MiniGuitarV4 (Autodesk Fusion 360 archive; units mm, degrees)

design "MiniGuitarV4" references "PCB"
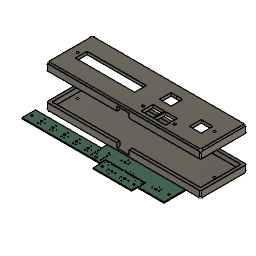
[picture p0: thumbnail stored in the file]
part number: 2026-04-06-11-56-48-601
part number: 2026-04-06-15-34-33-417
part number: 2026-04-06-15-34-33-425
part number: 2026-04-06-15-34-33-428
sketch "Sketch2" plane through (0, 0, 0) normal (0, 0, 1) x axis (1, 0, 0)
sketch "Sketch3" plane through (0, 0, 0) normal (0, 0, 1) x axis (1, 0, 0)
  line L1 (-63.5, -63.5) -> (-63.5, 12.7)
  line L2 (190.5, -63.5) -> (-63.5, -63.5)
  line L3 (190.5, 12.7) -> (190.5, -63.5)
  line L4 (-63.5, 12.7) -> (190.5, 12.7)
  point P2 (-63.5, 12.7)
  point P3 (-63.5, -63.5)
  point P4 (190.5, -63.5)
  vertical L1
  perpendicular L1 L2
  perpendicular L2 L3
  perpendicular L1 L4
  dimension "d1" distance P2 P3 = 76.2
  dimension "d2" distance P3 P4 = 254
extrude "Extrude2" new body sketch "Sketch3" along normal blind 25.4
sketch "Sketch4" plane through (0, -63.5, 0) normal (0, -1, 0) x axis (1, 0, 0)
  line L1 (190.5, 0) -> (-63.5, 0)
  line L2 (190.5, 25.4) -> (190.5, 0)
  line L3 (-63.5, 25.4) -> (190.5, 25.4)
  line L4 (-63.5, 0) -> (-63.5, 25.4)
  line L5 (127, 12.7) -> (25.4, 12.7)
  parallel L1 L5
split "Split1"
move "Move1"
shell "Shell1" innerThickness 5
shell "Shell2" innerThickness 5
component_insert "Component Insert"
position "Position1"
sketch "Sketch5" plane through (0, 0, 48.26) normal (0, 0, 1) x axis (-1, 0, 0)
  line L1 (63.5, -12.7) -> (-190.5, -12.7)
  line L2 (63.5, 63.5) -> (63.5, -12.7)
  line L3 (-190.5, 63.5) -> (63.5, 63.5)
  line L4 (-190.5, -12.7) -> (-190.5, 63.5)
position "Position2"
sketch "Sketch6" plane through (0, 0, 48.26) normal (0, 0, 1) x axis (-1, 0, 0)
sketch "Sketch7" plane through (0, 0, 48.26) normal (0, 0, 1) x axis (-1, 0, 0)
  line L1 (-56.2797, 13.1599) -> (52.7797, 13.1599)
  line L2 (-56.2797, 3.5) -> (-56.2797, 13.1599)
  line L3 (-185, 3.5) -> (-56.2797, 3.5)
  line L4 (-185, 40) -> (-185, 3.5)
  line L5 (-141.6791, 40) -> (-185, 40)
  line L6 (-141.6791, 27.4398) -> (-141.6791, 40)
  line L7 (-77.1395, 27.4398) -> (-141.6791, 27.4398)
  line L8 (-77.1395, 35.9798) -> (-77.1395, 27.4398)
  line L9 (52.6397, 35.9798) -> (-77.1395, 35.9798)
  line L10 (52.7797, 13.1599) -> (52.6397, 35.9798)
  horizontal L1
  perpendicular L1 L2
  perpendicular L2 L3
  perpendicular L3 L4
  perpendicular L4 L5
  perpendicular L5 L6
  perpendicular L4 L7
  perpendicular L7 L8
  perpendicular L4 L9
position "Position3"
hole "Hole3" HoleDepth 70 HoleDiameter 4 TipAngle 118
hole "Hole4" HoleDepth 70 HoleDiameter 4 TipAngle 118
position "Position4"
sketch "Sketch9" plane through (0, 0, 48.26) normal (0, 0, 1) x axis (-1, 0, 0)
  line L1 (63.5, -12.7) -> (-190.5, -12.7)
  line L2 (63.5, 63.5) -> (63.5, -12.7)
  line L3 (-190.5, 63.5) -> (63.5, 63.5)
  line L4 (-190.5, -12.7) -> (-190.5, 63.5)
  line L5 (44.2355, 15.4288) -> (44.2355, 24.9854)
  line L6 (-51.7645, 15.4288) -> (44.2355, 15.4288)
  line L7 (-51.7645, 34.5288) -> (-51.7645, 15.4288)
  line L8 (44.2355, 34.5288) -> (-51.7645, 34.5288)
  line L9 (44.2355, 24.9854) -> (44.2355, 34.5288)
  circle C1 centre (49.9355, 24.97) radius 2
  circle C2 centre (-174.9666, 25.162) radius 2
  point P9 (44.2355, 15.4288)
  point P10 (-51.7645, 15.4288)
  point P11 (-51.7645, 34.5288)
  perpendicular L5 L6
  perpendicular L6 L7
  perpendicular L7 L8
  dimension "d24" distance P9 P10 = 96
  dimension "d25" distance P10 P11 = 19.1
extrude "Extrude3" cut sketch "Sketch9" profile of L5 L6 L7 L8 L9 against normal blind 23
position "Position5"
sketch "Sketch10" plane through (0, 0, 48.26) normal (0, 0, 1) x axis (-1, 0, 0)
  line L1 (-51.7645, 34.5288) -> (-51.7645, 15.4288)
  line L2 (44.2355, 34.5288) -> (-51.7645, 34.5288)
  line L3 (44.2355, 15.4288) -> (44.2355, 34.5288)
  line L4 (-51.7645, 15.4288) -> (44.2355, 15.4288)
  line L5 (63.5, -12.7) -> (-190.5, -12.7)
  line L6 (63.5, 63.5) -> (63.5, -12.7)
  line L7 (-190.5, 63.5) -> (63.5, 63.5)
  line L8 (-190.5, -12.7) -> (-190.5, 63.5)
  line L9 (-53, 15.4288) -> (-51.7645, 15.4288)
  line L10 (-53, 34.5288) -> (-53, 15.4288)
  line L11 (-51.7645, 34.5288) -> (-53, 34.5288)
  line L12 (-51.7645, 34.5288) -> (-51.7645, 15.4288)
  circle C1 centre (49.9355, 24.97) radius 2
  circle C2 centre (-174.9666, 25.162) radius 2
  point P2 (-51.7645, 15.4288)
  point P12 (-51.7645, 15.4288)
  point P3 (-51.7645, 34.5288)
  point P15 (-51.7645, 34.5288)
  coincident P2 P12
  perpendicular L1 L9
  perpendicular L2 L10
  coincident P3 P15
  perpendicular L1 L11
extrude "Extrude4" cut sketch "Sketch10" profile of L1 L9 L10 L11 L12 against normal blind 11
sketch "Sketch11" plane through (0, 0, 48.26) normal (0, 0, 1) x axis (-1, 0, 0)
  line L1 (44.2355, 34.5288) -> (-53, 34.5288)
  line L2 (44.2355, 15.4288) -> (44.2355, 34.5288)
  line L3 (-53, 15.4288) -> (44.2355, 15.4288)
  line L4 (-53, 34.5288) -> (-53, 15.4288)
  line L5 (63.5, -12.7) -> (-190.5, -12.7)
  line L6 (63.5, 63.5) -> (63.5, -12.7)
  line L7 (-190.5, 63.5) -> (63.5, 63.5)
  line L8 (-190.5, -12.7) -> (-190.5, 63.5)
  line L9 (15.5414, 16) -> (15.5414, 15.4288)
  circle C1 centre (49.9355, 24.97) radius 2
  circle C2 centre (-174.9666, 25.162) radius 2
  point P12 (15.5414, 15.4288)
  coincident L3 P12
position "Position6"
sketch "Sketch12" plane through (0, 0, 48.26) normal (0, 0, 1) x axis (-1, 0, 0)
  line L1 (-181.768, 40) -> (-181.768, 4.4106)
  line L2 (-139, 40) -> (-181.768, 40)
  line L3 (-139, 27.7332) -> (-139, 40)
  line L4 (-73.5, 27.7332) -> (-139, 27.7332)
  line L5 (-73.5, 36.4659) -> (-73.5, 27.7332)
  line L6 (-54, 36.4659) -> (-73.5, 36.4659)
  line L7 (-54, 4.4) -> (-54, 36.4659)
  line L8 (-181.768, 4.4106) -> (-54, 4.4)
  vertical L1
  perpendicular L1 L2
  perpendicular L2 L3
  perpendicular L3 L4
  perpendicular L4 L5
  perpendicular L5 L6
  perpendicular L6 L7
sketch "Sketch13" plane through (0, 0, 48.26) normal (0, 0, 1) x axis (-1, 0, 0)
  line L1 (-83.7726, 5.2125) -> (-92.9726, 5.2125)
  line L2 (-83.7726, 24.2625) -> (-83.7726, 5.2125)
  line L3 (-102.8226, 24.2625) -> (-83.7726, 24.2625)
  line L4 (-102.8226, 5.2102) -> (-102.8226, 24.2625)
  line L5 (-92.9726, 5.2125) -> (-102.8226, 5.2102)
  point P2 (-92.9726, 5.2125)
  point P3 (-83.7726, 5.2125)
  point P4 (-83.7726, 24.2625)
  point P5 (-102.8226, 24.2625)
  perpendicular L1 L2
  perpendicular L2 L3
  perpendicular L3 L4
  dimension "d35" distance P2 P3 = 9.2
  dimension "d36" distance P3 P4 = 19.05
  dimension "d37" distance P4 P5 = 19.05
extrude "Extrude5" cut sketch "Sketch13" against normal blind 22
sketch "Sketch14" plane through (0, 0, 48.26) normal (0, 0, 1) x axis (-1, 0, 0)
  line L1 (-147.0576, 18.9528) -> (-147.0576, 28.4528)
  line L2 (-166.1076, 18.9528) -> (-147.0576, 18.9528)
  line L3 (-166.1076, 38.0028) -> (-166.1076, 18.9528)
  line L4 (-147.0576, 38.0028) -> (-166.1076, 38.0028)
  line L5 (-147.0576, 28.4528) -> (-147.0576, 38.0028)
  point P2 (-147.0576, 28.4528)
  point P3 (-147.0576, 18.9528)
  point P4 (-166.1076, 18.9528)
  point P5 (-166.1076, 38.0028)
  perpendicular L1 L2
  perpendicular L2 L3
  perpendicular L1 L4
  dimension "d42" distance P2 P3 = 9.5
  dimension "d43" distance P3 P4 = 19.05
  dimension "d44" distance P4 P5 = 19.05
extrude "Extrude6" cut sketch "Sketch14" against normal blind 10
move "Move2"
move "Move3"
sketch "Sketch15" plane through (0, -63.5, 0) normal (0, -1, 0) x axis (1, 0, 0)
  line L1 (190.5, 12.7003) -> (-63.5, 12.7003)
  line L2 (190.5, 25.4003) -> (190.5, 12.7003)
  line L3 (-63.5, 25.4003) -> (190.5, 25.4003)
  line L4 (-63.5, 12.7003) -> (-63.5, 25.4003)
  line L5 (73.7124, 22.9907) -> (136.9624, 22.9907)
  line L6 (73.7124, 2.2347) -> (73.7124, 22.9907)
  line L7 (136.9624, 2.2347) -> (73.7124, 2.2347)
  line L8 (136.9624, 22.9907) -> (136.9624, 2.2347)
  point P6 (136.9624, 22.9907)
  point P7 (73.7124, 22.9907)
  point P8 (73.7124, 2.2347)
  perpendicular L1 L6
  perpendicular L6 L7
  perpendicular L5 L8
  dimension "d47" distance P6 P7 = 63.25
  dimension "d48" distance P7 P8 = 20.756
sketch "Sketch18" plane through (0, -63.5, 0) normal (0, -1, 0) x axis (1, 0, 0)
  line L1 (137, 12.2) -> (137, 23)
  line L2 (130.6, 12.2) -> (137, 12.2)
  point P2 (137, 23)
  point P3 (137, 12.2)
  point P4 (130.6, 12.2)
  vertical L1
  perpendicular L1 L2
  dimension "d49" distance P2 P3 = 10.8
  dimension "d50" distance P3 P4 = 6.4
sketch "Sketch23" plane through (0, 0, 25.4003) normal (0, 0, 1) x axis (-1, 0, 0)
  line L1 (-166.1076, 38.0028) -> (-166.1076, 18.9528)
  line L2 (-147.0576, 38.0028) -> (-166.1076, 38.0028)
  line L3 (-147.0576, 18.9528) -> (-147.0576, 38.0028)
  line L4 (-166.1076, 18.9528) -> (-147.0576, 18.9528)
  line L5 (-92.9726, 5.2125) -> (-83.7726, 5.2125)
  line L6 (-102.8226, 5.2102) -> (-92.9726, 5.2125)
  line L7 (-102.8226, 24.2625) -> (-102.8226, 5.2102)
  line L8 (-83.7726, 24.2625) -> (-102.8226, 24.2625)
  line L9 (-83.7726, 5.2125) -> (-83.7726, 24.2625)
  line L10 (44.2355, 34.5288) -> (-53, 34.5288)
  line L11 (44.2355, 15.4288) -> (44.2355, 34.5288)
  line L12 (-53, 15.4288) -> (44.2355, 15.4288)
  line L13 (-53, 34.5288) -> (-53, 15.4288)
  line L14 (63.5, -12.7) -> (-190.5, -12.7)
  line L15 (63.5, 63.5) -> (63.5, -12.7)
  line L16 (-190.5, 63.5) -> (63.5, 63.5)
  line L17 (-190.5, -12.7) -> (-190.5, 63.5)
  line L18 (-74.4161, 57.1431) -> (-74.4161, 36.3931)
  line L19 (-137.9161, 57.1431) -> (-74.4161, 57.1431)
  line L20 (-137.9161, 36.3931) -> (-137.9161, 57.1431)
  line L21 (-74.4161, 36.3931) -> (-137.9161, 36.3931)
  circle C1 centre (49.9355, 24.97) radius 2
  circle C2 centre (-174.9666, 25.162) radius 2
  point P21 (-74.4161, 36.3931)
  point P22 (-74.4161, 57.1431)
  point P23 (-137.9161, 57.1431)
  perpendicular L12 L18
  perpendicular L18 L19
  perpendicular L19 L20
  perpendicular L18 L21
  dimension "d98" distance P21 P22 = 20.75
  dimension "d99" distance P22 P23 = 63.5
sketch "Sketch24" plane through (0, 0, 25.4003) normal (0, 0, 1) x axis (-1, 0, 0)
  line L1 (-74.4, 47.2) -> (-74.4, 36.4)
  line L2 (-79.9, 47.2) -> (-74.4, 47.2)
  point P2 (-74.4, 36.4)
  point P3 (-74.4, 47.2)
  point P4 (-79.9, 47.2)
  vertical L1
  perpendicular L1 L2
  dimension "d101" distance P2 P3 = 10.8
  dimension "d102" distance P3 P4 = 5.5
hole "Hole7" HoleDepth 10 HoleDiameter 4 TipAngle 118
position "Position7"
sketch "Sketch25" plane through (0, 0, 25.4003) normal (0, 0, 1) x axis (-1, 0, 0)
  line L1 (-137.92, 47.19) -> (-137.92, 36.39)
  line L2 (-131.42, 47.19) -> (-137.92, 47.19)
  point P2 (-137.92, 36.39)
  point P3 (-137.92, 47.19)
  point P4 (-131.42, 47.19)
  vertical L1
  perpendicular L1 L2
  dimension "d107" distance P2 P3 = 10.8
  dimension "d108" distance P3 P4 = 6.5
hole "Hole8" HoleDepth 10 HoleDiameter 4 TipAngle 118
sketch "Sketch26" plane through (0, 0, 25.4003) normal (0, 0, 1) x axis (-1, 0, 0)
  line L1 (-85.6081, 36.8917) -> (-85.6081, 46.3917)
  line L2 (-104.6581, 36.8917) -> (-85.6081, 36.8917)
  line L3 (-104.6581, 55.9417) -> (-104.6581, 36.8917)
  line L4 (-85.6081, 55.9417) -> (-104.6581, 55.9417)
  line L5 (-85.6081, 46.3917) -> (-85.6081, 55.9417)
  line L6 (-106.6081, 36.8917) -> (-116.1081, 36.8917)
  line L7 (-106.6081, 55.9417) -> (-106.6081, 36.8917)
  line L8 (-125.6581, 55.9417) -> (-106.6081, 55.9417)
  line L9 (-125.6581, 36.8917) -> (-125.6581, 55.9417)
  line L10 (-116.1081, 36.8917) -> (-125.6581, 36.8917)
  point P2 (-85.6081, 46.3917)
  point P3 (-85.6081, 36.8917)
  point P4 (-104.6581, 36.8917)
  point P5 (-104.6581, 55.9417)
  point P7 (-116.1081, 36.8917)
  point P8 (-106.6081, 36.8917)
  point P9 (-106.6081, 55.9417)
  point P10 (-125.6581, 55.9417)
  perpendicular L2 L3
  perpendicular L3 L4
  perpendicular L3 L6
  perpendicular L6 L7
  perpendicular L7 L8
  perpendicular L8 L9
  dimension "d115" distance P2 P3 = 9.5
  dimension "d116" distance P3 P4 = 19.05
  dimension "d117" distance P4 P5 = 19.05
  dimension "d120" distance P7 P8 = 9.5
  dimension "d124" distance P8 P9 = 19.05
  dimension "d125" distance P9 P10 = 19.05
extrude "Extrude12" cut sketch "Sketch26" profile of L1 L2 L3 L4 L5 against normal blind 6
extrude "Extrude13" cut sketch "Sketch26" profile of L6 L7 L8 L9 L10 against normal blind 9
fillet "Fillet2" radius 2
move "Move8"
extrude "Extrude14" new body sketch "Sketch23" profile of L18 L19 L20 L21 along normal blind 2
move "Move9"
component_from_bodies "Body->Comp1"
component_from_bodies "Body->Comp2"
component_from_bodies "Body->Comp3"
position "Position8"
sketch "Sketch27" plane through (0, -63.5, 0) normal (0, -1, 0) x axis (1, 0, 0)
  line L1 (-61.5, 2.7003) -> (-61.5, 11.4006)
  line L2 (188.5, 2.7003) -> (-61.5, 2.7003)
  line L3 (188.5, 11.4006) -> (188.5, 2.7003)
  line L4 (-59.5003, 13.4003) -> (186.5003, 13.4003)
  line L5 (52.9404, 10) -> (72.9404, 10)
  line L6 (52.9404, -5) -> (52.9404, 10)
  line L7 (72.9404, -5) -> (52.9404, -5)
  line L8 (72.9404, 10) -> (72.9404, -5)
  arc A1 centre (186.5003, 11.4006) radius 1.9997 clockwise from (186.5003, 13.4003) to (188.5, 11.4006)
  arc A2 centre (-59.5003, 11.4006) radius 1.9997 clockwise from (-61.5, 11.4006) to (-59.5003, 13.4003)
  point P10 (72.9404, 10)
  point P11 (52.9404, 10)
  perpendicular L4 L6
  perpendicular L5 L8
  dimension "d135" distance P10 P11 = 20
extrude "Extrude1" cut sketch "Sketch27" profile of L2 L5 L6 L7 L8 against normal blind 10
position "Position9"
sketch "Sketch28" plane through (0, 0, 0) normal (0, 0, 1) x axis (1, 0, 0)
  line L1 (28, 51) -> (13, 51)
  line L2 (28, 36) -> (28, 51)
  line L3 (13, 36) -> (28, 36)
  line L4 (13, 51) -> (13, 36)
  point P2 (13, 51)
  point P3 (28, 51)
  point P4 (28, 36)
  horizontal L1
  perpendicular L1 L2
  perpendicular L2 L3
  perpendicular L1 L4
  dimension "d140" distance P2 P3 = 15
  dimension "d141" distance P3 P4 = 15
extrude "Extrude15" new body sketch "Sketch28" along normal blind 8
move "Move10"
move "Move1"
move "Move11"
position "Position10"
position "Position11"
sketch "Sketch30" plane through (0, 0, -5) normal (0, 0, 1) x axis (-1, 0, 0)
  line L1 (-185.5, 58.5) -> (-72.9404, 58.5)
  line L2 (-185.5, -7.7) -> (-185.5, 58.5)
  line L3 (58.5, -7.7) -> (-185.5, -7.7)
  line L4 (58.5, 58.5) -> (58.5, -7.7)
  line L5 (-52.9404, 58.5) -> (58.5, 58.5)
  line L6 (-52.9404, 63.5) -> (-52.9404, 58.5)
  line L7 (-72.9404, 63.5) -> (-52.9404, 63.5)
  line L8 (-72.9404, 58.5) -> (-72.9404, 63.5)
  line L9 (53, 28) -> (53, 22)
  line L10 (47, 28) -> (53, 28)
  line L11 (47, 22) -> (47, 28)
  line L12 (53, 22) -> (47, 22)
  line L13 (-177.5, 27.5) -> (-177.5, 22.5)
  line L14 (-172.5, 27.5) -> (-177.5, 27.5)
  line L15 (-172.5, 22.5) -> (-172.5, 27.5)
  line L16 (-177.5, 22.5) -> (-172.5, 22.5)
  circle C1 centre (49.9355, 24.97) radius 2
  circle C2 centre (-174.9666, 25.162) radius 2
  vertical L9
  perpendicular L9 L10
  perpendicular L10 L11
  perpendicular L11 L12
  vertical L13
  perpendicular L13 L14
  perpendicular L14 L15
  perpendicular L13 L16
move "Move12"
position "Position12"
extrude "Extrude2" add sketch "Sketch30" profile of C1 L9 L10 L11 L12 along normal blind 11.5
extrude "Extrude3" add sketch "Sketch30" profile of C2 L13 L14 L15 L16 along normal blind 11.5
position "Position13"
hole "Hole1" HoleDepth 10 HoleDiameter 4 TipAngle 118
hole "Hole2" HoleDepth 10 HoleDiameter 4 TipAngle 118
position "Position14"
sketch "Sketch33" plane through (0, 0, -5) normal (0, 0, 1) x axis (-1, 0, 0)
  line L1 (-177.5, 22.5) -> (-172.5, 22.5)
  line L2 (-177.5, 27.5) -> (-177.5, 22.5)
  line L3 (-172.5, 27.5) -> (-177.5, 27.5)
  line L4 (-172.5, 22.5) -> (-172.5, 27.5)
  line L5 (47, 28) -> (47, 22)
  line L6 (53, 28) -> (47, 28)
  line L7 (53, 22) -> (53, 28)
  line L8 (47, 22) -> (53, 22)
  line L9 (-185.5, 58.5) -> (-72.9404, 58.5)
  line L10 (-185.5, -7.7) -> (-185.5, 58.5)
  line L11 (58.5, -7.7) -> (-185.5, -7.7)
  line L12 (58.5, 58.5) -> (58.5, -7.7)
  line L13 (-52.9404, 58.5) -> (58.5, 58.5)
  line L14 (-52.9404, 63.5) -> (-52.9404, 58.5)
  line L15 (-72.9404, 63.5) -> (-52.9404, 63.5)
  line L16 (-72.9404, 58.5) -> (-72.9404, 63.5)
  line L17 (-77.5, 50) -> (-77.5, 44.5)
  line L18 (-82.5, 50) -> (-77.5, 50)
  line L19 (-82.5, 44.5) -> (-82.5, 50)
  line L20 (-77.5, 44.5) -> (-82.5, 44.5)
  line L21 (-128.5, 44.5) -> (-134, 44.5)
  line L22 (-128.5, 50) -> (-128.5, 44.5)
  line L23 (-134, 50) -> (-128.5, 50)
  line L24 (-134, 44.5) -> (-134, 50)
  circle C1 centre (-131.4342, 47.2053) radius 2
  circle C2 centre (-79.9022, 47.1967) radius 2
  vertical L17
  perpendicular L17 L18
  perpendicular L18 L19
  perpendicular L17 L20
  horizontal L21
  perpendicular L21 L22
  perpendicular L22 L23
  perpendicular L21 L24
extrude "Extrude4" add sketch "Sketch33" profile of C1 L21 L22 L23 L24 along normal blind 11.5
extrude "Extrude5" add sketch "Sketch33" profile of C2 L17 L18 L19 L20 along normal blind 11.5
position "Position15"
sketch "Sketch34" plane through (0, -63.5, 0) normal (0, -1, 0) x axis (1, 0, 0)
  line L1 (72.9404, 2.7004) -> (72.9404, 10.0001)
  line L2 (188.5, 2.7004) -> (72.9404, 2.7004)
  line L3 (188.5, 11.4007) -> (188.5, 2.7004)
  line L4 (-59.5003, 13.4004) -> (186.5003, 13.4004)
  line L5 (-61.5, 2.7004) -> (-61.5, 11.4007)
  line L6 (52.9404, 2.7004) -> (-61.5, 2.7004)
  line L7 (52.9404, 10.0001) -> (52.9404, 2.7004)
  line L8 (72.9404, 10.0001) -> (52.9404, 10.0001)
  line L9 (74.9274, -6.3881) -> (74.9274, 11.9777)
  arc A1 centre (186.5003, 11.4007) radius 1.9997 clockwise from (186.5003, 13.4004) to (188.5, 11.4007)
  arc A2 centre (-59.5003, 11.4007) radius 1.9997 clockwise from (-61.5, 11.4007) to (-59.5003, 13.4004)
  perpendicular L2 L9
move "Move13"
position "Position16"
split "Split1"
hole "Hole5" HoleDepth 10 HoleDiameter 4 TipAngle 118
sketch "Sketch19" plane through (0, -63.5, 0) normal (0, -1, 0) x axis (1, 0, 0)
  line L1 (73.7, 12.2) -> (73.7, 23)
  line L2 (79.2, 12.2) -> (73.7, 12.2)
  point P2 (73.7, 23)
  point P3 (73.7, 12.2)
  point P4 (79.2, 12.2)
  vertical L1
  perpendicular L1 L2
  dimension "d54" distance P2 P3 = 10.8
  dimension "d55" distance P3 P4 = 5.5
hole "Hole6" HoleDepth 10 HoleDiameter 4 TipAngle 118
sketch "Sketch20" plane through (0, -63.5, 0) normal (0, -1, 0) x axis (1, 0, 0)
  line L1 (94.4, 23) -> (73.7, 23)
  line L2 (84.9, 22.5) -> (84.9, 13)
  line L3 (103.95, 22.5) -> (84.9, 22.5)
  line L4 (103.95, 3.45) -> (103.95, 22.5)
  line L5 (84.9, 3.45) -> (103.95, 3.45)
  line L6 (84.9, 13) -> (84.9, 3.45)
  line L7 (105.9, 22.5) -> (105.9, 13)
  line L8 (124.95, 22.5) -> (105.9, 22.5)
  line L9 (124.95, 3.45) -> (124.95, 22.5)
  line L10 (105.9, 3.45) -> (124.95, 3.45)
  line L11 (105.9, 13) -> (105.9, 3.45)
  point P2 (73.7, 23)
  point P3 (94.4, 23)
  point P4 (84.9, 13)
  point P5 (84.9, 22.5)
  point P6 (103.95, 22.5)
  point P7 (103.95, 3.45)
  point P8 (84.9, 3.45)
  point P9 (105.9, 13)
  point P10 (105.9, 22.5)
  point P11 (124.95, 22.5)
  point P12 (124.95, 3.45)
  horizontal L1
  perpendicular L1 L2
  perpendicular L2 L3
  perpendicular L3 L4
  perpendicular L4 L5
  perpendicular L7 L8
  perpendicular L8 L9
  perpendicular L9 L10
  perpendicular L10 L11
  dimension "d59" distance P2 P3 = 20.7
  dimension "d77" distance P4 P5 = 9.5
  dimension "d78" distance P5 P6 = 19.05
  dimension "d79" distance P6 P7 = 19.05
  dimension "d80" distance P7 P8 = 19.05
  dimension "d83" distance P9 P10 = 9.5
  dimension "d84" distance P10 P11 = 19.05
  dimension "d85" distance P11 P12 = 19.05
sketch "Sketch21" plane through (0, -63.5, 0) normal (0, -1, 0) x axis (1, 0, 0)
sketch "Sketch22" plane through (0, -63.5, 0) normal (0, -1, 0) x axis (1, 0, 0)
extrude "Extrude8" cut sketch "Sketch20" profile of L2 L3 L4 L5 L6 against normal blind 10
extrude "Extrude9" cut sketch "Sketch20" profile of L7 L8 L9 L10 L11 against normal blind 10
move "Move4"
extrude "Extrude10" new body sketch "Sketch15" profile of L1 L5 L6 L7 L8 along normal blind 2
move "Move5"
move "Move6"
move "Move7"
fillet "Fillet1" radius 2
extrude "Extrude11" cut of existing geometry blind -1
extrude "Extrude7" cut sketch "Sketch20" profile of L2 L3 L4 L5 L6 against normal blind 9
hole "Hole1" HoleDepth 70 HoleDiameter 4 TipAngle 118
hole "Hole2" HoleDepth 70 HoleDiameter 4 TipAngle 118
sketch "Sketch8" plane through (0, 0, 48.26) normal (0, 0, 1) x axis (-1, 0, 0)
extrude "Extrude1" new body sketch "Sketch3" along normal blind 31.75
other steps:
base_feature "Base Feature1"
base_feature "Base Feature1"
base_feature "Base Feature1"
extrude "Extrude1" cut sketch "Sketch27" profile of L2 L5 L6 L7 L8 against normal blind 10
split "Split1"
create_component "CreateComponent1"
reparent_decal "ReparentDecal1"
remove_body "RemoveBody1"
create_component "CreateComponent2"
reparent_decal "ReparentDecal2"
remove_body "RemoveBody2"
create_component "CreateComponent3"
reparent_decal "ReparentDecal3"
remove_body "RemoveBody3"

design "PCB"
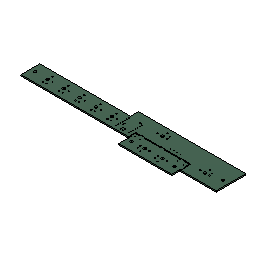
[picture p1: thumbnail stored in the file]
description: KiCad electronic assembly
part number: .step 1
description: Part Number
part number: GuitarController_PCB
base_feature "Base Feature"
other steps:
create_component "CreateComponent1"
